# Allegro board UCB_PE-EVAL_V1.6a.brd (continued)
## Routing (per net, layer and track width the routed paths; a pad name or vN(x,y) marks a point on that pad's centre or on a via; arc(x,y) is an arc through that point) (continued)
SPI_CS: length 28.9
  TOP w0.254: ADC1.3 v1(10.83,42.39)
  BOTTOM w0.254: v1(10.83,42.39) 10.83,43.78 8.13,46.48 6.1,46.48 5.33,47.24 5.33,64.26 J1.26
SPI_DIN: length 27.8
  TOP w0.254: ADC1.2 v1(13.82,43.04)
  LAYER3 w0.254: J1.23 v1(11.78,62.99)
  BOTTOM w0.254: v1(11.78,62.99) 11.94,62.84 11.94,43.83 12.73,43.04 v1(13.82,43.04)
SPI_DOUT: length 42.5
  TOP w0.254: ADC1.18 19.94,42.39 19.97,42.42 v1(21.08,42.42)
  LAYER3 w0.254: v1(21.08,64.01) 20.3,64.01 20.21,64.1 8.55,64.1 8.38,64.26 5.33,64.26 J1.24
  BOTTOM w0.254: v1(21.08,42.42) 21.08,43.2 20.8,43.49 20.8,61.44 21.08,61.72 v1(21.08,64.01)
SPI_SCLK: length 25.7
  TOP w0.254: ADC1.1 11.68,43.69 11.08,44.29 v1(11.08,45.36)
  BOTTOM w0.254: J1.25 7.84,65.53 10.92,62.45 10.92,51.05 11.18,50.8 11.18,46.23 11.08,46.14 v1(11.08,45.36)
SW_1: length 85.9
  TOP w0.254: 37.72,4.32 38.57,4.32 ; 38.57,4.32 38.86,4.61 38.86,7.87 27.69,7.87 24.13,11.43 13.21,11.43 9.91,14.73 9.91,21.47 5.33,26.04 5.33,59.18 J1.21 ; 38.57,4.32 R79.1
SW_2: length 89.3
  TOP w0.254: R78.1 37.72,9.4
  LAYER3 w0.254: J1.22 5.22,61.61 12.08,61.61 13.76,63.29 19.49,63.29 19.54,63.25 v1(20.32,63.25)
  BOTTOM w0.254: 37.72,9.4 37.72,33.91 36.07,35.56 21.84,35.56 20.07,37.34 20.07,61.7 20.32,61.96 v1(20.32,63.25)
V_ADC4: length 13
  TOP w0.254: JP4.2 48.81,48.51 48.68,48.64 R63.1 ; R63.1 44.36,47.4 43.94,46.99 U24.2 ; R63.1 44.36,50.15 C78.1
V_BOOST: length 11.6
  TOP w0.254: 52.96,20.7 52.96,21.97 52.83,22.1 R64.1
  TOP w0.635: R16.1 52.96,20.7 55.37,23.11 C35.1
V_BUCK: length 16.3
  TOP w0.254: 77.6,19.69 77.6,21.72 77.72,21.84 R58.2
  TOP w0.635: U6.2 U6.1 ; C4.1 84.36,21.08 78.99,21.08 77.6,19.69 R15.1
V_L2: length 2.5
  BOTTOM w0.635: R46.1 J3.2
V_L3: length 2.5
  BOTTOM w0.635: R52.1 J3.3
VA: length 2.5
  BOTTOM w0.635: R40.1 J3.1
VBK_SRC: length 99
  TOP w0.254: 83.44,64.52 83.69,64.26 89.41,64.26 89.92,64.77 89.92,69.09 88.9,70.1 60.5,70.1 59.94,70.66 59.94,78.35 61.09,79.49 C24.2
  TOP w0.635: C24.2 61.09,81.23 58.67,83.64 58.67,87.88 59.18,88.39 64.9,88.39 65.53,89.03 65.53,90.09 D13.2 67.7,90.17 TX1.3 ; U11.5 87.13,58.42 v1(83.57,58.42) 83.44,58.55 83.44,67.18 84.07,67.82 C39.2 ; 92.83,53.09 Q7.3 93.22,53.09
  BOTTOM w0.635: Q7.3 90.3,55.88 86.11,55.88 v1(83.57,58.42)
VMID1: length 81.4
  TOP w0.635: Q1.3 114.17,91.31 111.13,94.36 U8.5 109.35,95.88 105.66,99.57 C36.2 ; v1(110.49,91.69) 106.68,91.69 105.16,90.17 98.55,90.17 v1(96.01,87.63) 94.87,87.63 C21.2 ; D10.2 81.66,84.54 TX1.7 75.23,84.54 v1(72.64,87.12)
  LAYER3 w0.635: v1(96.01,87.63) 96.01,84.58 93.47,82.04 77.72,82.04 v1(72.64,87.12)
VMID2: length 92.9
  TOP w0.635: Q3.3 137.18,91.31 133.74,94.75 U9.5 132.24,95.88 128.14,99.98 C37.2 ; D11.2 82.2,86.54 TX1.8 v1(76.45,86.54) ; C22.2 v1(96.01,91.44)
  LAYER3 w0.635: v1(76.45,86.54) 77.65,85.34 89.92,85.34 v1(96.01,91.44) 100.33,91.44 105.92,85.85 127,85.85 130.56,89.41 v1(130.56,90.42)
  BOTTOM w0.254: 138.94,75.69 138.94,75.82 Q4.2 ; 138.94,91.06 Q3.3
VMID3: length 119.4
  TOP w0.635: v1(76.45,89.66) 77.58,88.54 TX1.9 80.03,88.52 D12.2 ; C23.2 v1(96.01,95.25) ; Q5.3 158.88,91.31 155.83,94.36 U10.5 155.47,95.88 153.92,97.43 153.92,105.02 154.94,106.03 C38.2
  LAYER3 w0.635: v1(76.45,89.66) 76.45,92.46 81.53,97.54 93.73,97.54 v1(96.01,95.25) 101.6,95.25 107.44,89.41 124.21,89.41 128.27,93.47 131.57,93.47 135.38,89.66 153.42,89.66 v1(155.45,91.69)
VPOT: length 57
  TOP w0.254: v1(43.97,35) 44.84,34.13 R72.1
  LAYER3 w0.254: v1(43.97,35) 43.19,35 43.02,35.17 16.61,35.17 15.79,34.35 v1(10.92,34.35)
  BOTTOM w0.254: R74.2 14.55,18.96 14.55,21.26 12.19,23.62 12.19,34.09 11.94,34.35 v1(10.92,34.35)
N07970: length 3.8
  TOP w0.254: R9.2 R8.2 78.23,79.36 U3.3
N08403: length 5.3
  TOP w0.254: U3.5 80.34,78.36 80.77,78.8 80.77,81.66 80.52,81.91 C18.1
N08410: length 2.5
  TOP w0.254: R10.2 85.78,78.49 85.65,78.36 U3.12
N08443: length 4.7
  TOP w0.254: U3.10 84.74,77.36 86.47,75.63 C19.2
N08455: length 2.8
  TOP w0.254: U3.11 85,77.86 85.78,77.09 R11.2
N08467: length 6
  TOP w0.254: C20.2 93.24,76.95 93.1,77.09 R11.1
N09759: length 20.1
  TOP w0.254: v1(81.53,77.98) 80.92,77.36 U3.7 ; R14.2 73.41,74.68 v1(74.42,73.66)
  TOP w0.635: R14.2 72.64,75.07 71.25,76.46 Q9.1 Q9.2 Q9.3
  BOTTOM w0.254: v1(81.53,77.98) 81.53,76.96 78.23,73.66 v1(74.42,73.66)
N09873: length 39.4
  TOP w0.254: R12.2 85.9,81.79 85.39,81.28 82.55,81.28 80.76,83.07 76.12,83.07 76.11,83.06 69.46,83.06
  TOP w0.635: Q9.6 67.84,80.26 Q9.9 ; Q9.6 Q9.7 ; Q9.6 Q9.5 ; Q9.9 68.48,82.08 70.61,84.21 70.61,87.61 69.69,88.54 TX1.4 ; Q9.9 67.84,78.99 Q9.7 ; Q9.8 Q9.7
N10901: length 15.6
  TOP w0.254: v1(72.64,82.3) 72.64,81.99 72.19,81.53 Q9.4 ; v1(78.49,75.69) 78.49,77.51 78.84,77.86 U3.6
  BOTTOM w0.254: v1(72.64,82.3) 72.64,78.74 75.69,75.69 v1(78.49,75.69)
N10913: length 5.2
  TOP w0.254: R12.1 88.15,81.03 87.9,80.77 85.34,80.77 84.94,80.36 U3.16
N10917: length 2.7
  TOP w0.254: U3.14 84.74,79.36 85.26,79.88 R13.1
N11491: length 2.9
  TOP w0.635: TX1.12 80.99,95.5 D7.2
N11495: length 2.7
  TOP w0.635: TX1.11 80.57,93.09 D6.2
N11499: length 2.6
  TOP w0.635: TX1.10 80.29,90.81 D5.2
N11507: length 2.7
  TOP w0.635: D8.2 67.86,84.33 TX1.6
N11532: length 2.6
  TOP w0.635: D9.2 67.99,86.61 TX1.5
N38522: length 4
  TOP w0.635: R15.2 77.6,11.1 78.11,10.59 D17.2
N38634: length 3.3
  TOP w0.635: D18.2 52.83,11.76 52.96,11.89 R16.2
N41110: length 3.7
  TOP w0.254: U6.6 85.63,16.13 86.36,16.86 86.36,17.95 86.12,18.19 C50.1
N41352: length 3.8
  TOP w0.254: C51.1 60.46,16.11 59.73,15.37 U7.6
N42617: length 3.6
  TOP w1.27: D1.2 64.26,97.61 JP2.1
N42649: length 3.8
  TOP w1.27: JP2.2 61.72,97.1 D1.1
N48243: length 24.5
  TOP w0.254: 24.64,81.42 24.64,81.15 24.89,80.9 R37.2 ; 24.64,81.42 24.64,81.42 R35.2 ; 24.64,81.42 24.47,81.25 v1(24.47,79.63) C62.2 ; U16.3 14.27,67.45 14.38,67.56 v1(14.99,67.56)
  LAYER3 w0.254: v1(14.99,67.56) 16.11,68.69 16.11,74.28 17.54,75.71 20.55,75.71 v1(24.47,79.63)
N48256: length 3.1
  TOP w0.254: R35.1 27.65,82.17 28.92,80.9 U20.7
N48260: length 3.1
  TOP w0.254: U20.6 28.92,82.17 27.65,83.44 R36.1
N48264: length 31.1
  TOP w0.254: 13.96,83.36 14.14,83.36 R38.1 ; 13.96,83.36 13.96,82.19 ; 13.96,83.36 15.17,84.58 24.68,84.58 25.39,83.87 R36.2 ; U16.2 11.91,68.1 11.43,68.58 11.43,79.66 13.96,82.19 ; 13.96,82.19 14.1,82.19 C61.1
N48807: length 18.9
  TOP w0.254: U20.2 42.23,80.9 ; 42.23,80.9 42.23,82.42 ; 42.23,80.9 49.66,80.9 51.31,82.55 R33.2 51.31,85.08 ; 42.23,82.42 42.23,83.95 C58.1 ; 42.23,82.42 R39.1
N51115: length 29.1
  TOP w0.254: 23.11,72.39 23.11,74.93 23.37,75.18 R43.2 ; 23.11,72.39 R41.2 ; 23.11,72.39 23.11,72.39 23.11,71.42 ; v1(14.91,64.85) 14.91,65.72 14.48,66.15 U16.5 ; 23.11,71.42 23.67,70.87 C67.2 ; 23.11,71.42 22.8,71.12 21.08,71.12 v1(20.32,71.88)
  LAYER3 w0.254: v1(14.91,64.85) 16.2,64.85 16.22,64.83 16.8,64.83 16.82,64.85 18.37,64.85 21.24,67.72 21.24,70.96 v1(20.32,71.88)
N51119: length 2.4
  TOP w0.254: U21.7 28.17,72.52 28.04,72.39 R41.1
N51123: length 2.4
  TOP w0.254: R42.1 U21.6
N51127: length 41.1
  TOP w0.254: v1(24.14,74.14) 24.5,73.79 R42.2 ; v1(17.4,74.27) 17.4,80.9 17.02,81.28 14.73,81.28 14.21,80.76 R44.1 C66.1 ; U16.6 10.7,65.5 10.17,66.03 v1(10.17,75.95)
  LAYER3 w0.254: v1(24.14,74.14) 23.36,74.14 23.23,74.27 v1(17.4,74.27)
  BOTTOM w0.254: v1(17.4,74.27) 16.48,75.18 10.93,75.18 v1(10.17,75.95)
N51265: length 146.8
  TOP w0.254: v1(50.8,72.52) 47.62,72.52 47.24,72.9 ; 47.24,72.9 47.24,73.15 46.36,74.04 R45.1 C63.1 ; 47.24,72.9 47.24,71.37 46.74,70.87 42.45,70.87 40.8,72.52 U21.2
  LAYER2 w0.254: v1(50.8,72.52) 53.72,69.6 104.9,69.6 111,63.5 111,22.35 v1(108.97,20.32)
  BOTTOM w0.254: v1(108.97,20.32) 108.97,19.54 114.53,13.97 R40.2
N52251: length 12.7
  TOP w0.254: U16.10 24.29,66.15 24.82,66.68 R49.2 25.91,66.68 26.21,66.37 26.21,64.06 26.16,64.01 ; 26.16,64.01 R47.2 ; 26.16,64.01 26.16,63.04 25.51,62.4 C72.2
N52255: length 2.4
  TOP w0.254: R47.1 U22.7
N52259: length 2.4
  TOP w0.254: U22.6 R48.1
N52263: length 24.6
  TOP w0.254: v1(16.51,65.53) 17.29,65.53 17.32,65.5 U16.9 24.59,65.5 24.82,65.28 R48.2 ; R50.1 C71.1 13.51,76.45 12.95,75.9 v1(12.95,73.15)
  BOTTOM w0.254: v1(12.95,73.15) 12.95,71.1 13.39,70.67 14.17,70.67 14.62,70.22 15.66,70.22 16.51,69.36 v1(16.51,65.53)
N52429: length 133.3
  TOP w0.254: U22.2 41.43,64.01 42.47,62.97 42.47,62.94 43.18,62.23 45.47,62.23 46.48,63.25 v1(46.48,65.53) R51.1 C68.1
  LAYER2 w0.254: v1(53.34,36.83) 75.44,36.83 v1(77.98,34.29)
  BOTTOM w0.254: R46.2 131.83,14.99 129.79,17.02 118.36,17.02 101.09,34.29 v1(77.98,34.29) ; v1(53.34,36.83) 46.74,43.43 46.74,63.33 46.48,63.58 v1(46.48,65.53)
N53429: length 27.2
  TOP w0.254: U16.12 20.14,67.45 v1(20.14,67.92) ; R55.2 25.13,60.97 24.89,61.21 22.86,61.21 v1(22.61,60.96) 22.61,54.1 23.11,53.59 24.05,53.59 24.43,53.98 C77.2 R53.2
  BOTTOM w0.254: v1(20.14,67.92) 20.98,67.92 21.84,67.06 21.84,61.72 v1(22.61,60.96)
N53433: length 2.7
  TOP w0.254: U23.7 R53.1
N53437: length 2.7
  TOP w0.254: U23.6 R54.1
N53441: length 33.3
  TOP w0.254: U16.13 17.9,68.1 17.6,68.41 17.6,71.11 v1(17.05,71.66) 16.49,72.21 14.72,72.21 14.21,72.72 C76.1 R56.1 ; R54.2 24.43,57.02 24.13,57.33 v1(24.13,60.2)
  LAYER3 w0.254: v1(24.13,60.2) 24.68,60.75 24.68,69.79 21.78,72.7 18.08,72.7 v1(17.05,71.66)
N53607: length 179.5
  TOP w0.254: U23.2 40.8,55.75 43.67,52.89 46.29,52.89 v1(48.77,55.37) 47.32,55.37 45.16,57.53 R57.1 C73.1
  LAYER2 w0.254: v1(48.77,55.37) 47.5,54.1 v1(47.5,4.57)
  LAYER3 w0.254: v1(47.5,4.57) 49.78,2.29 109.98,2.29 115.82,8.13 v1(117.86,8.13)
  BOTTOM w0.254: R52.2 138.68,13.97 140.46,12.19 140.46,4.83 139.19,3.56 124.21,3.56 119.63,8.13 v1(117.86,8.13)
N54653: length 30.4
  TOP w0.254: 24.62,46.23 24.63,46.23 R59.2 ; 24.62,46.23 v1(24.58,46.23) 23.11,46.23 21.34,48.01 21.34,50.04 23.37,52.07 24.62,52.07 25.39,51.31 R61.2 ; 24.62,46.23 C82.2 ; U17.3 v1(14.38,49.29)
  LAYER3 w0.254: v1(24.58,46.23) 14.98,46.23 13.83,47.38 13.83,48.74 v1(14.38,49.29)
N54657: length 2.5
  TOP w0.254: U24.7 R59.1
N54661: length 2.5
  TOP w0.254: U24.6 R60.1
N54665: length 34.1
  TOP w0.254: R60.2 24.38,48.26 23.62,49.02 v1(23.62,51.31) ; v1(15.49,50.8) 14.71,50.8 13.85,49.94 U17.2 11.46,49.94 11.18,50.23 11.18,58.55 13.46,60.83 C81.1 R62.1
  LAYER3 w0.254: v1(23.62,51.31) 23.62,52.83 23.37,53.09 17.78,53.09 v1(15.49,50.8)
N56809: length 29.7
  TOP w0.254: R65.2 C87.2 23.88,35.81 23.11,36.58 23.11,39.62 23.75,40.26 R67.2 25.01,42.05 21.59,45.47 14.99,45.47 14.48,44.96 12.7,44.96 11.18,46.48 11.18,47.4 11.77,47.99 U17.5
N56813: length 2.9
  TOP w0.254: U25.7 R65.1
N56817: length 2.9
  TOP w0.254: U25.6 R66.1
N56821: length 35.5
  TOP w0.254: 19.6,46.26 20.57,47.23 20.57,51.82 15.12,57.27 15.12,58.31 ; 19.6,46.26 19.31,45.97 15.75,45.97 14.38,47.34 U17.6 ; 19.6,46.26 21.81,46.26 25.86,42.21 25.86,39.49 25.36,38.99 R66.2 ; 15.12,58.31 14.99,58.31 C86.1 ; 15.12,58.31 14.97,58.46 R68.1
N56959: length 22.8
  TOP w0.254: U25.2 44.07,37.72 44.28,37.93 44.48,37.93 ; R64.2 52.83,27.43 v1(51.56,28.7) ; 44.48,37.93 44.62,37.93 v1(51.56,30.99) ; 44.48,37.93 R69.1 44.48,40.75 C83.1
  LAYER2 w0.254: v1(51.56,30.99) v1(51.56,28.7)
N58569: length 33
  TOP w0.254: C88.1 R71.1 R70.2 21.61,31.24 20.07,29.7 20.07,28.45 v1(19.3,27.69) ; v1(16.51,48.01) 16.52,47.99 U17.10
  BOTTOM w0.254: v1(16.51,48.01) 15.49,46.99 15.49,37.85 15.93,37.41 15.93,28.78 17.02,27.69 v1(19.3,27.69)
N59411: length 47.3
  TOP w0.254: C89.1 R73.1 R72.2 36.45,31.37 33.57,34.25 v1(33.57,49.29) ; U17.12 v1(16.51,49.29)
  LAYER3 w0.254: v1(16.51,49.29) v1(33.57,49.29)
N62015: length 1.8
  BOTTOM w0.635: U26.6 124.46,105.53 C94.1
N71004: length 24.2
  TOP w0.254: 15.24,30.73 15,30.49 C102.2 ; 15.24,30.73 15.24,32.34 ; 15.24,30.73 15.55,31.04 U27.6 18.2,31.04 R75.2 ; 15.24,32.34 U27.8 ; 15.24,32.34 14.8,32.34 v1(13.71,31.25) ; ADC1.7 11.62,39.79 11.45,39.62 v1(10.67,39.62)
  BOTTOM w0.254: v1(10.67,39.62) 10.67,38.35 10.16,37.85 10.16,35.56 10.41,35.31 12.19,35.31 14.26,33.24 14.26,31.8 v1(13.71,31.25)
N72702: length 2.9
  TOP w0.254: SW8.6 R76.2
N72714: length 2.9
  TOP w0.254: SW8.4 R77.2
N72726: length 11.8
  TOP w0.254: U28.4 35.12,12.03 33.68,13.46 29.72,13.46 29.46,13.21 29.46,9.79 29.86,9.4 R77.1
N72730: length 21.9
  TOP w0.254: U28.6 37.52,10.92 40.13,10.92 40.69,10.36 40.69,3.76 39.98,3.05 31.31,3.05 30.7,3.66 R76.1
N126025: length 3.1
  TOP w0.254: R80.2 D19.2
N126027: length 2.9
  TOP w0.254: D25.2 R86.2
N126029: length 2.9
  TOP w0.254: D24.2 R85.2
N126031: length 2.9
  TOP w0.254: D23.2 R84.2
N126033: length 3.1
  TOP w0.254: R83.2 D22.2
N126035: length 2.9
  TOP w0.254: D26.2 R87.2
N126037: length 3.1
  TOP w0.254: R82.2 D21.2
N126039: length 3.1
  TOP w0.254: D20.2 R81.2
N176335: length 2.7
  TOP w0.254: U1.6 108.12,10.79 108.51,11.19 C47.1
N176535: length 3
  TOP w0.254: 108.97,43.56 110.15,43.56 110.55,43.95 C48.1
N176547: length 2.3
  TOP w0.254: U5.6 156.35,32.64 156.49,32.78 C49.1
N179536: length 3.7
  TOP w0.635: U8.2 R17.2
N179712: length 4.7
  TOP w0.635: U9.2 123.34,100.97 123.21,100.84 R19.2
N179920: length 3.9
  TOP w0.635: U10.2 R21.2
N180096: length 3.8
  TOP w0.635: R23.2 U11.2
N180288: length 3.7
  TOP w0.635: R25.2 102.23,82.93
N180476: length 3.7
  TOP w0.635: R27.2 124.84,82.93
N180632: length 3.7
  TOP w0.635: R29.2 146.93,82.93
N180804: length 4.8
  TOP w0.254: R31.2 52.98,34.54 52.99,34.54 53.57,34.54 53.58,34.54 53.94,34.54 54.7,33.78 U15.2
N180846: length 9.2
  TOP w0.635: R32.1 67.06,34.04 66.8,33.78 U15.7 U15.6
N220911: length 2.7
  TOP w0.254: C104.1 156.74,42.68 156.35,42.29 U29.6
N223775: length 2.7
  TOP w0.254: C105.1 62.51,65.8 62.12,65.41 U30.6
N248745: length 1.9
  TOP w0.254: U31.6 78.59,52.06 C108.1
N283243: length 155.4
  TOP w0.254: R88.1 v1(134.87,107.95)
  LAYER3 w0.254: v1(42.8,96.39) 46.99,100.58 73.66,100.58 76.96,103.89 95.5,103.89 101.6,109.98 133.86,109.98 134.87,108.97 v1(134.87,107.95)
  BOTTOM w0.254: v1(42.8,96.39) 42.8,94.62 49.78,87.63 49.78,54.1 48.51,52.83 48.51,47.5 JP4.3
N283252: length 74.8
  TOP w0.254: R58.1 76.45,25.65 v1(75.95,26.16)
  LAYER2 w0.254: v1(92.58,44.96) 85.09,37.46 85.09,31.75 79.5,26.16 v1(75.95,26.16)
  LAYER3 w0.254: JP4.1 51.77,51.05 55.84,46.99 90.55,46.99 v1(92.58,44.96)

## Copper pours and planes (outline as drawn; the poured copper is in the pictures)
18V_GL on LAYER2: 163.58,88.9 102.62,88.9 102.62,87.12 163.58,87.12
GND on TOP: 92.46,23.11 89.66,23.11 89.66,25.65 87.12,25.65 84.07,22.61 80.26,22.61 80.26,24.89 83.57,24.89 86.11,27.43 91.44,27.43 92.46,26.42
GND on TOP: 92.71,0.76 92.71,9.91 89.66,9.91 89.66,3.56 66.55,3.56 66.55,8.64 62.48,8.64 62.48,0.76
GND on TOP: 163.58,74.42 114.3,74.42 114.3,67.82 163.58,67.82
GND on TOP: 143.76,110.24 152.4,110.24 153.16,109.47 153.16,67.82 148.59,67.82 148.59,106.43 143.76,106.43
GND on TOP: 143.76,107.44 147.83,107.44 147.83,113.54 85.85,113.54 85.85,104.14 90.42,104.14 90.42,109.98 90.68,110.24 143.76,110.24
GND on BOTTOM: 71.63,29.97 65.28,29.97 65.28,26.92 61.72,26.92 61.72,22.1 67.82,22.1 68.58,22.86 68.58,25.91 70.87,25.91 71.63,26.67
GND on BOTTOM: 42.16,109.73 42.16,104.9 42.67,104.39 52.32,104.39 56.39,100.33 63.75,100.33 63.75,107.44 46.74,107.44 44.45,109.73
GND on BOTTOM: 78.99,107.19 74.17,107.19 74.17,102.36 66.55,94.74 66.55,60.2 70.61,60.2 70.61,94.74 78.99,103.12
GND on BOTTOM: 70.61,66.04 65.28,66.04 65.28,27.18 89.66,27.18 89.66,4.83 92.71,4.83 92.71,29.97 68.83,29.97 68.83,58.42 70.61,60.2
GND on BOTTOM: 58.67,107.44 63.75,107.44 63.75,104.39 67.31,104.39 70.1,107.19 82.04,107.19 82.04,104.14 72.14,104.14 68.33,100.33 58.67,100.33
GND on BOTTOM: 78.99,107.19 85.09,107.19 87.88,109.98 90.42,109.98 90.42,104.14 78.99,104.14
GND_SIGNAL on LAYER2: 0.76,88.65 7.37,88.65 7.37,97.28 26.91,97.28 26.94,91.46 34.29,91.42 34.29,27.18 42.42,27.18 42.42,0.76 0.76,0.76
GND_SIGNAL on LAYER2: 148.34,99.06 99.82,99.06 99.82,97.79 148.34,97.79
GND_SIGNAL on LAYER2: 148.08,81.03 99.57,81.03 99.57,79.76 148.08,79.76
VIN on TOP: 85.34,110.74 82.8,110.74 82.8,98.04 85.34,98.04
VIN on TOP: 57.91,66.29 53.09,66.29 53.09,73.91 54.36,75.18 56.39,75.18 57.91,73.66
VIN on TOP: 41.15,99.06 36.58,99.06 36.58,109.73 41.15,109.73
VIN on TOP: 95.25,56.64 75.18,56.64 74.68,57.15 60.45,57.15 60.45,54.61 95.25,54.61
VIN on TOP: 36.58,103.89 36.58,99.06 43.43,99.06 48.01,94.49 48.01,88.14 54.86,88.14 54.86,94.49 45.47,103.89
VIN on BOTTOM: 53.09,75.18 57.91,75.18 57.91,57.15 64.26,57.15 64.26,54.36 53.09,54.36
VIN on BOTTOM: 41.15,99.06 36.58,99.06 36.58,113.28 45.72,113.28 48.26,110.74 85.34,110.74 85.34,108.2 46.74,108.2 44.7,110.24 41.15,110.24
VIN on BOTTOM: 41.15,104.65 36.58,104.65 36.58,99.06 49.02,99.06 53.09,95 53.09,66.29 57.91,66.29 57.91,96.01 50.04,103.89 41.91,103.89
DC_LINK on BOTTOM: 163.58,95.25 114.3,95.25 114.3,92.96 163.58,92.96
DC_LINK on BOTTOM: 143.76,92.96 140.72,92.96 140.72,110.24 123.95,110.24 123.95,113.54 143.76,113.54
IGBT_G1 on TOP: 118.87,95.5 114.55,95.5 114.55,101.85 118.87,101.85
IGBT_G2 on TOP: 118.87,77.47 114.55,77.47 114.55,83.82 118.87,83.82
IGBT_G3 on TOP: 141.48,95.5 137.16,95.5 137.16,101.85 141.48,101.85
IGBT_G4 on TOP: 141.48,77.47 137.16,77.47 137.16,83.82 141.48,83.82
IGBT_G5 on TOP: 163.58,95.5 159.26,95.5 159.26,101.85 163.58,101.85
IGBT_G6 on TOP: 163.58,77.47 159.26,77.47 159.26,83.82 163.58,83.82
IGBT_G7 on TOP: 95.25,57.15 91.44,57.15 91.44,63.75 95.25,63.75
V_BOOST on TOP: 68.83,22.61 73.91,22.61 73.91,12.45 63.75,12.45 63.75,14.48 68.83,14.48 68.83,20.07 57.91,20.07 57.91,24.64 61.47,24.64 61.47,21.84 68.07,21.84
V_BUCK on TOP: 89.92,40.39 95.5,40.39 95.5,12.95 89.66,12.95 89.66,15.24 92.71,15.24 92.71,20.07 85.6,20.07 85.6,23.62 87.38,25.4 88.9,25.4 89.41,24.89 89.41,22.61 92.71,22.61 92.71,35.31 90.68,37.34 89.92,37.34
V_L1 on TOP: 102.36,11.68 98.04,11.68 98.04,33.78 102.36,38.1 102.36,43.94 105.66,43.94 105.66,36.58 102.36,33.27
V_L1 on TOP: 105.66,43.94 102.36,43.94 102.36,37.85 103.38,36.83 119.89,36.83 119.89,40.13 107.19,40.13 105.66,41.66
V_L2 on TOP: 150.37,33.02 130.05,33.02 123.44,26.42 123.44,19.05 134.11,19.05 134.11,25.65 135.89,27.43 147.83,27.43 150.37,29.97
V_L2 on TOP: 134.11,26.16 123.44,26.16 123.44,19.05 129.54,12.95 129.54,3.56 134.11,3.56
V_L3 on TOP: 150.37,42.67 143.76,42.67 143.76,37.08 146.81,37.08 150.37,40.64
V_L3 on TOP: 143.76,37.08 160.78,37.08 160.78,29.72 155.96,24.89 155.96,18.03 160.78,18.03 160.78,23.88 164.08,27.18 164.08,39.62 143.76,39.62
V_L3 on TOP: 135.38,3.56 135.38,15.24 144.02,23.88 160.78,23.88 160.78,18.03 146.56,18.03 141.48,12.95 141.48,3.56
VA on TOP: 102.36,11.18 98.04,11.18 98.04,2.29 128.27,2.29 128.27,9.65 127.51,10.41 124.21,10.41 124.21,9.65 120.4,5.84 103.89,5.84 102.36,7.37
VBK_SRC on TOP: 89.66,51.56 83.57,51.56 83.57,49.28 88.14,44.7 95.25,51.82 95.25,54.1 92.2,54.1
VBK_SRC on TOP: 95.25,54.1 92.2,54.1 80.52,42.42 80.52,25.4 82.55,25.4 82.55,38.86 95.25,51.56
VMID1 on BOTTOM: 118.87,92.46 108.46,92.46 107.19,91.19 107.19,62.99 103.38,59.18 103.38,49.78 114.3,60.71 114.3,74.42 118.87,74.42 118.87,77.22 114.3,77.22 114.3,88.9 118.87,88.9
VMID2 on BOTTOM: 141.48,92.46 131.06,92.46 129.79,91.19 129.79,66.04 123.7,59.94 123.7,50.29 136.91,63.5 136.91,74.42 141.48,74.42 141.48,77.22 136.91,77.22 136.91,88.9 141.48,88.9
VMID3 on BOTTOM: 163.58,92.46 153.16,92.46 151.89,91.19 151.89,66.8 144.27,59.18 144.27,48.77 159,63.5 159,74.42 163.58,74.42 163.58,77.22 159,77.22 159,88.9 163.58,88.9
N38590 on TOP: 68.83,32.51 68.83,29.97 71.88,29.97 71.88,26.67 70.87,25.65 68.83,25.65 68.83,23.11 73.91,23.11 73.91,32.51
N38590 on TOP: 68.83,53.85 73.91,53.85 73.91,29.97 68.83,29.97 68.83,32.51 71.63,32.51 71.63,51.05 68.83,51.05
N38702 on TOP: 91.95,15.75 91.95,17.78 87.38,17.78 86.87,17.27 86.87,12.19 83.31,8.64 83.31,4.32 86.11,4.32 89.15,7.37 89.15,15.49 89.41,15.75
N38762 on TOP: 65.79,14.99 65.79,17.02 61.21,17.02 61.21,11.68 59.69,11.68 57.4,9.4 57.4,5.33 60.96,5.33 60.96,9.4 63.5,9.4 63.5,14.99
N42617 on TOP: 63.75,107.44 68.83,107.44 68.83,101.09 80.52,101.09 80.52,96.52 63.75,96.52
N42649 on TOP: 61.98,96.27 61.98,99.57 53.59,107.95 53.59,113.54 49.02,113.54 49.02,106.43 59.18,96.27
N62666 on BOTTOM: 123.44,110.24 123.44,113.03 122.94,113.54 92.71,113.54 90.42,111.25 90.93,110.74 90.93,105.16 96.01,105.16 96.01,110.24
N62666 on BOTTOM: 90.42,111.25 82.8,111.25 82.8,113.54 96.01,113.54 96.01,105.16 90.93,105.16 90.93,110.74
N176863 on TOP: 150.37,33.53 135.64,33.53 131.57,37.59 131.57,52.58 138.43,59.44 142.24,59.44 142.24,36.32 142.75,35.81 150.37,35.81
N176875 on TOP: 145.03,43.18 150.37,43.18 150.37,46.74 157.99,54.36 164.34,54.36 164.34,59.94 157.48,59.94 145.03,47.5
N176963 on TOP: 102.36,44.45 105.66,44.45 105.66,46.23 114.3,54.86 123.44,54.86 123.44,59.44 113.54,59.44 102.36,48.26
N179562 on TOP: 109.98,101.85 109.98,97.79 114.05,97.79 114.05,101.85
N179754 on TOP: 132.59,101.85 132.59,97.79 136.65,97.79 136.65,101.85
N179946 on TOP: 154.69,101.85 154.69,97.79 158.75,97.79 158.75,101.85
N180138 on TOP: 90.68,63.75 86.61,63.75 86.61,59.69 90.68,59.69
N180330 on TOP: 109.98,83.82 109.98,79.76 114.05,79.76 114.05,83.82
N180502 on TOP: 132.59,83.82 132.59,79.76 136.65,79.76 136.65,83.82
N180674 on TOP: 154.69,83.82 154.69,79.76 158.75,79.76 158.75,83.82
N223929 on TOP: 57.91,65.79 53.09,65.79 53.09,52.07 54.1,51.05 57.15,51.05 57.91,51.82
N249090 on TOP: 85.6,52.07 85.6,54.1 82.8,54.1 80.77,52.07 80.77,47.5 76.45,43.18 76.45,37.34 76.71,37.08 79.25,37.08 79.5,37.34 79.5,42.16 83.06,45.72 83.06,51.56 83.57,52.07

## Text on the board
Ref Des/Silkscreen Top: User I/O | Boost Converter | + | 9V-36V | - | Buck Converter | UCB_PE-EVAL | V1.6A | Chris Farnell | 27Jun2019 | Ia | 3-Phase Inverter | A | B | C | I_L1 | I_A | I_L2 | I_L3 | DC | ADC_Sel | I_L4
